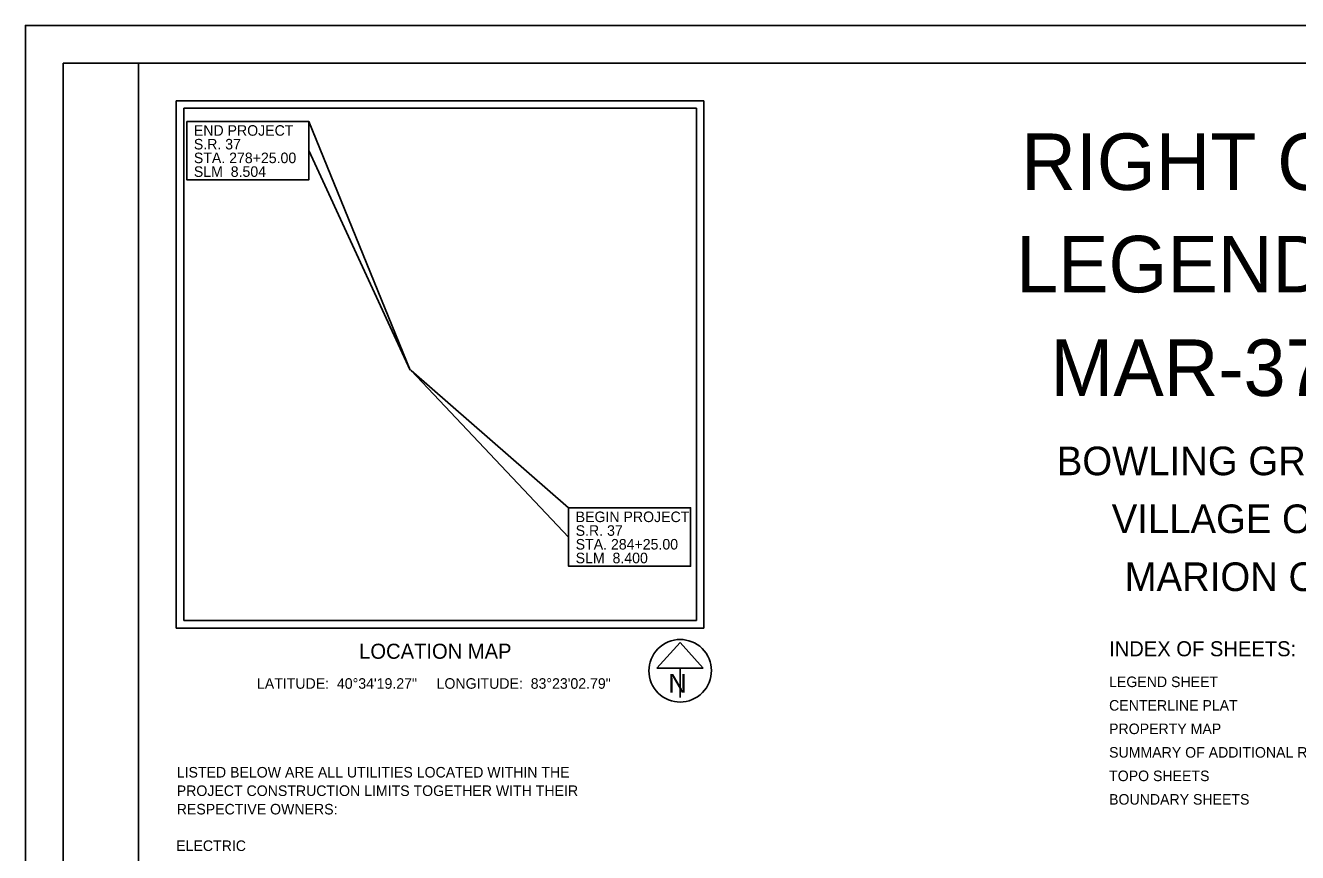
# Model space of a CAD drawing. Extents: x 0 to 59.1, y -2.4 to 22.
# Drawn here: x 0 to 16.87, y 11.02 to 22 of the extents above; entities that cross this region are included whole.
import ezdxf

# ---------------------------------------------------------------- set-up
doc = ezdxf.new("R2010")
doc.units = 0
for name, color, linetype in [('SH_Border', 7, 'Continuous'), ('SH_Cut_Line', 7, 'Continuous'), ('SH_Data', 7, 'Continuous'), ('SH_Text', 7, 'Continuous')]:
    doc.layers.add(name, color=color, linetype=linetype)

msp = doc.modelspace()

# ---------------------------------------------------------------- linework, layer by layer
at = {"layer": 'SH_Border'}
for points in [[(0.5, 21.5), (1.5, 21.5), (1.5, 0.5), (0.5, 0.5)], [(1.5, 21.5), (33.5, 21.5), (33.5, 0.5), (1.5, 0.5)]]:
    msp.add_lwpolyline(points, close=True, dxfattribs=at)
at = {"layer": 'SH_Cut_Line'}
msp.add_lwpolyline([(0, 0), (34, 0), (34, 22), (0, 22)], close=True, dxfattribs=at)
at = {"layer": 'SH_Data'}
for p, q in [((2, 21), (9, 21)), ((2, 21), (2, 14)), ((9, 21), (9, 14)), ((2.1, 20.9), (2.1, 14.1)), ((2.1, 20.9), (8.9, 20.9)), ((8.9, 20.9), (8.9, 14.1)), ((2.1, 14.1), (8.9, 14.1)), ((2, 14), (9, 14)), ((8.685, 13.809), (8.377, 13.468)), ((8.992, 13.468), (8.685, 13.809)), ((8.377, 13.468), (8.992, 13.468)), ((8.685, 13.468), (8.685, 13.081)), ((8.685, 13.435), (8.685, 13.435)), ((8.685, 13.435), (8.685, 13.435))]:
    msp.add_line(p, q, dxfattribs=at)
for points in [[(2.141, 20.727), (3.759, 20.727), (3.759, 19.95), (2.141, 19.95)], [(5.104, 17.425), (3.759, 20.727), (3.759, 20.338)], [(7.206, 15.599), (5.115, 17.421), (7.206, 15.21)], [(7.206, 15.599), (8.824, 15.599), (8.824, 14.821), (7.206, 14.821)]]:
    msp.add_lwpolyline(points, close=True, dxfattribs=at)
msp.add_arc((8.685, 13.435), 0.415, 129.7798, 129.7633, dxfattribs=at)

# ---------------------------------------------------------------- texts
for s, height, p in [('END PROJECT', 0.14, (2.234, 20.536)), ('S.R. 37', 0.14, (2.234, 20.354)), ('RIGHT OF WAY', 0.75, (13.21, 19.816)), ('STA. 278+25.00', 0.14, (2.234, 20.172)), ('SLM  8.504', 0.14, (2.234, 19.99)), ('LEGEND SHEET', 0.75, (13.141, 18.457)), ('MAR-37-8.44', 0.75, (13.596, 17.082)), ('BOWLING GREEN TWP. &', 0.38, (13.681, 16.03)), ('BEGIN PROJECT', 0.14, (7.299, 15.408)), ('VILLAGE OF LA RUE', 0.38, (14.41, 15.262)), ('S.R. 37', 0.14, (7.299, 15.226)), ('STA. 284+25.00', 0.14, (7.299, 15.044)), ('SLM  8.400', 0.14, (7.299, 14.862)), ('MARION COUNTY', 0.38, (14.581, 14.493)), ('INDEX OF SHEETS:', 0.2, (14.375, 13.627)), ('N', 0.25, (8.529, 13.144)), ('LEGEND SHEET', 0.14, (14.375, 13.218)), ('CENTERLINE PLAT', 0.14, (14.375, 12.906)), ('PROPERTY MAP', 0.14, (14.375, 12.594)), ('SUMMARY OF ADDITIONAL R/W', 0.14, (14.375, 12.282)), ('TOPO SHEETS', 0.14, (14.375, 11.97)), ('BOUNDARY SHEETS', 0.14, (14.375, 11.658))]:
    msp.add_text(s, height=height, dxfattribs=at).set_placement(p)
at = {"layer": 'SH_Text'}
for s, height, p in [('LOCATION MAP', 0.2, (4.427, 13.594)), ('LATITUDE:  40°34\'19.27"     LONGITUDE:  83°23\'02.79"', 0.14, (3.071, 13.196)), ('LISTED BELOW ARE ALL UTILITIES LOCATED WITHIN THE', 0.14, (2.007, 12.018)), ('PROJECT CONSTRUCTION LIMITS TOGETHER WITH THEIR', 0.14, (2.007, 11.773)), ('RESPECTIVE OWNERS:', 0.14, (2.007, 11.528)), ('ELECTRIC', 0.14, (2, 11.043))]:
    msp.add_text(s, height=height, dxfattribs=at).set_placement(p)

doc.saveas('drawing.dxf')
